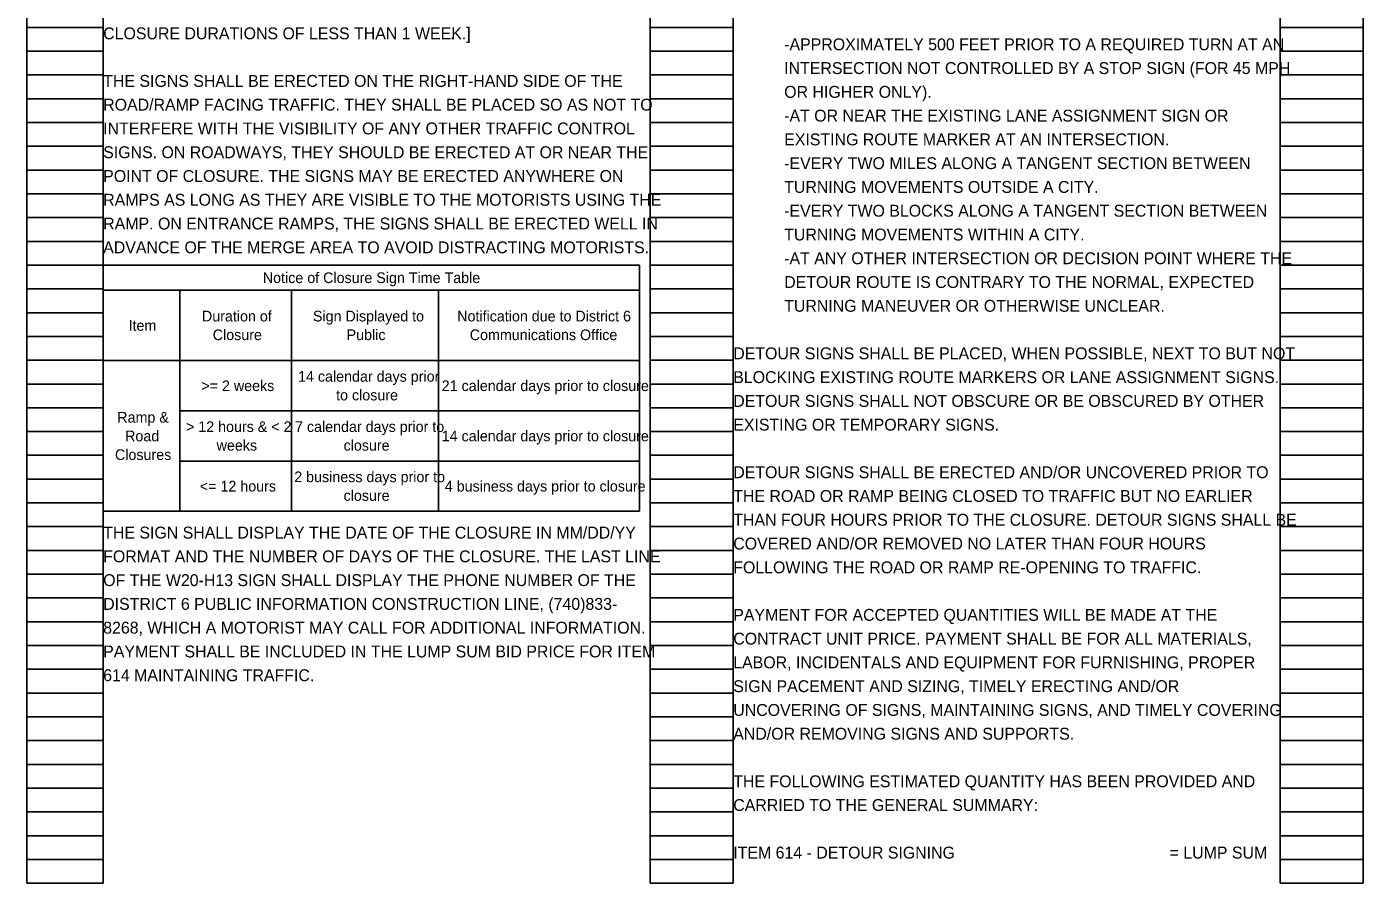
# Model space of a CAD drawing. Extents: x 24172 to 24226.9, y 11011.9 to 11091.2.
# Drawn here: x 24196.45 to 24212.19, y 11041.95 to 11052.04 of the extents above; entities that cross this region are included whole.
import ezdxf

# ---------------------------------------------------------------- set-up
doc = ezdxf.new("R2010")
doc.units = 0
doc.layers.add('SC_Scratch1', color=7, linetype='Continuous')
doc.layers.add('SH_Data', color=7, linetype='Continuous')

msp = doc.modelspace()

# ---------------------------------------------------------------- linework, layer by layer
at = {"layer": 'SC_Scratch1'}
for p, q in [((24197.35, 11049.227), (24203.665, 11049.227)), ((24197.35, 11049.227), (24197.35, 11046.328)), ((24203.665, 11049.227), (24203.665, 11046.328)), ((24197.35, 11048.931), (24203.665, 11048.931)), ((24198.252, 11048.931), (24198.252, 11046.328)), ((24199.568, 11048.931), (24199.568, 11046.328)), ((24201.299, 11048.931), (24201.299, 11046.328)), ((24197.35, 11048.103), (24203.665, 11048.103)), ((24198.252, 11047.511), (24203.665, 11047.511)), ((24198.252, 11046.919), (24203.665, 11046.919)), ((24197.35, 11046.328), (24203.665, 11046.328))]:
    msp.add_line(p, q, dxfattribs=at)
at = {"layer": 'SH_Data'}
for p, q in [((24196.45, 11041.947), (24196.45, 11062.107)), ((24197.35, 11041.947), (24197.35, 11062.107)), ((24203.79, 11041.947), (24203.79, 11062.107)), ((24204.77, 11041.947), (24204.77, 11062.107)), ((24211.21, 11041.947), (24211.21, 11062.107)), ((24212.19, 11041.947), (24212.19, 11062.107)), ((24196.45, 11052.027), (24197.35, 11052.027)), ((24203.79, 11052.027), (24204.77, 11052.027)), ((24211.21, 11052.027), (24212.19, 11052.027)), ((24196.45, 11051.747), (24197.35, 11051.747)), ((24203.79, 11051.747), (24204.77, 11051.747)), ((24211.21, 11051.747), (24212.19, 11051.747)), ((24196.45, 11051.467), (24197.35, 11051.467)), ((24203.79, 11051.467), (24204.77, 11051.467)), ((24211.21, 11051.467), (24212.19, 11051.467)), ((24196.45, 11051.187), (24197.35, 11051.187)), ((24203.79, 11051.187), (24204.77, 11051.187)), ((24211.21, 11051.187), (24212.19, 11051.187)), ((24196.45, 11050.907), (24197.35, 11050.907)), ((24203.79, 11050.907), (24204.77, 11050.907)), ((24211.21, 11050.907), (24212.19, 11050.907)), ((24196.45, 11050.627), (24197.35, 11050.627)), ((24203.79, 11050.627), (24204.77, 11050.627)), ((24211.21, 11050.627), (24212.19, 11050.627)), ((24196.45, 11050.347), (24197.35, 11050.347)), ((24203.79, 11050.347), (24204.77, 11050.347)), ((24211.21, 11050.347), (24212.19, 11050.347)), ((24196.45, 11050.067), (24197.35, 11050.067)), ((24203.79, 11050.067), (24204.77, 11050.067)), ((24211.21, 11050.067), (24212.19, 11050.067)), ((24196.45, 11049.787), (24197.35, 11049.787)), ((24203.79, 11049.787), (24204.77, 11049.787)), ((24211.21, 11049.787), (24212.19, 11049.787)), ((24196.45, 11049.507), (24197.35, 11049.507)), ((24203.79, 11049.507), (24204.77, 11049.507)), ((24211.21, 11049.507), (24212.19, 11049.507)), ((24196.45, 11049.227), (24197.35, 11049.227)), ((24203.79, 11049.227), (24204.77, 11049.227)), ((24211.21, 11049.227), (24212.19, 11049.227)), ((24196.45, 11048.947), (24197.35, 11048.947)), ((24203.79, 11048.947), (24204.77, 11048.947)), ((24211.21, 11048.947), (24212.19, 11048.947)), ((24196.45, 11048.667), (24197.35, 11048.667)), ((24203.79, 11048.667), (24204.77, 11048.667)), ((24211.21, 11048.667), (24212.19, 11048.667)), ((24196.45, 11048.387), (24197.35, 11048.387)), ((24203.79, 11048.387), (24204.77, 11048.387)), ((24211.21, 11048.387), (24212.19, 11048.387)), ((24196.45, 11048.107), (24197.35, 11048.107)), ((24203.79, 11048.107), (24204.77, 11048.107)), ((24211.21, 11048.107), (24212.19, 11048.107)), ((24196.45, 11047.827), (24197.35, 11047.827)), ((24203.79, 11047.827), (24204.77, 11047.827)), ((24211.21, 11047.827), (24212.19, 11047.827)), ((24196.45, 11047.547), (24197.35, 11047.547)), ((24203.79, 11047.547), (24204.77, 11047.547)), ((24211.21, 11047.547), (24212.19, 11047.547)), ((24196.45, 11047.267), (24197.35, 11047.267)), ((24203.79, 11047.267), (24204.77, 11047.267)), ((24211.21, 11047.267), (24212.19, 11047.267)), ((24196.45, 11046.987), (24197.35, 11046.987)), ((24203.79, 11046.987), (24204.77, 11046.987)), ((24211.21, 11046.987), (24212.19, 11046.987)), ((24196.45, 11046.707), (24197.35, 11046.707)), ((24203.79, 11046.707), (24204.77, 11046.707)), ((24211.21, 11046.707), (24212.19, 11046.707)), ((24196.45, 11046.427), (24197.35, 11046.427)), ((24203.79, 11046.427), (24204.77, 11046.427)), ((24211.21, 11046.427), (24212.19, 11046.427)), ((24196.45, 11046.147), (24197.35, 11046.147)), ((24203.79, 11046.147), (24204.77, 11046.147)), ((24211.21, 11046.147), (24212.19, 11046.147)), ((24196.45, 11045.867), (24197.35, 11045.867)), ((24203.79, 11045.867), (24204.77, 11045.867)), ((24211.21, 11045.867), (24212.19, 11045.867)), ((24196.45, 11045.587), (24197.35, 11045.587)), ((24203.79, 11045.587), (24204.77, 11045.587)), ((24211.21, 11045.587), (24212.19, 11045.587)), ((24196.45, 11045.307), (24197.35, 11045.307)), ((24203.79, 11045.307), (24204.77, 11045.307)), ((24211.21, 11045.307), (24212.19, 11045.307)), ((24196.45, 11045.027), (24197.35, 11045.027)), ((24203.79, 11045.027), (24204.77, 11045.027)), ((24211.21, 11045.027), (24212.19, 11045.027)), ((24196.45, 11044.747), (24197.35, 11044.747)), ((24203.79, 11044.747), (24204.77, 11044.747)), ((24211.21, 11044.747), (24212.19, 11044.747)), ((24196.45, 11044.467), (24197.35, 11044.467)), ((24203.79, 11044.467), (24204.77, 11044.467)), ((24211.21, 11044.467), (24212.19, 11044.467)), ((24196.45, 11044.187), (24197.35, 11044.187)), ((24203.79, 11044.187), (24204.77, 11044.187)), ((24211.21, 11044.187), (24212.19, 11044.187)), ((24196.45, 11043.907), (24197.35, 11043.907)), ((24203.79, 11043.907), (24204.77, 11043.907)), ((24211.21, 11043.907), (24212.19, 11043.907)), ((24196.45, 11043.627), (24197.35, 11043.627)), ((24203.79, 11043.627), (24204.77, 11043.627)), ((24211.21, 11043.627), (24212.19, 11043.627)), ((24196.45, 11043.347), (24197.35, 11043.347)), ((24203.79, 11043.347), (24204.77, 11043.347)), ((24211.21, 11043.347), (24212.19, 11043.347)), ((24196.45, 11043.067), (24197.35, 11043.067)), ((24203.79, 11043.067), (24204.77, 11043.067)), ((24211.21, 11043.067), (24212.19, 11043.067)), ((24196.45, 11042.787), (24197.35, 11042.787)), ((24203.79, 11042.787), (24204.77, 11042.787)), ((24211.21, 11042.787), (24212.19, 11042.787)), ((24196.45, 11042.507), (24197.35, 11042.507)), ((24203.79, 11042.507), (24204.77, 11042.507)), ((24211.21, 11042.507), (24212.19, 11042.507)), ((24196.45, 11042.227), (24197.35, 11042.227)), ((24203.79, 11042.227), (24204.77, 11042.227)), ((24211.21, 11042.227), (24212.19, 11042.227)), ((24196.45, 11041.947), (24197.35, 11041.947)), ((24203.79, 11041.947), (24204.77, 11041.947)), ((24211.21, 11041.947), (24212.19, 11041.947))]:
    msp.add_line(p, q, dxfattribs=at)

# ---------------------------------------------------------------- texts
at = {"layer": 'SC_Scratch1'}
for s, height, p in [('CLOSURE DURATIONS OF LESS THAN 1 WEEK.]', 0.14, (24197.35, 11051.887)), ('.', 0.14, (24201.438, 11051.887)), ('-APPROXIMATELY 500 FEET PRIOR TO A REQUIRED TURN AT AN ', 0.14, (24205.37, 11051.758)), ('INTERSECTION NOT CONTROLLED BY A STOP SIGN (FOR 45 MPH ', 0.14, (24205.37, 11051.478)), ('THE SIGNS SHALL BE ERECTED ON THE RIGHT-HAND SIDE OF THE ', 0.14, (24197.35, 11051.327)), ('OR HIGHER ONLY).', 0.14, (24205.37, 11051.198)), ('ROAD/RAMP FACING TRAFFIC. THEY SHALL BE PLACED SO AS NOT TO ', 0.14, (24197.35, 11051.047)), ('-AT OR NEAR THE EXISTING LANE ASSIGNMENT SIGN OR ', 0.14, (24205.37, 11050.918)), ('INTERFERE WITH THE VISIBILITY OF ANY OTHER TRAFFIC CONTROL ', 0.14, (24197.35, 11050.767)), ('EXISTING ROUTE MARKER AT AN INTERSECTION.', 0.14, (24205.37, 11050.638)), ('SIGNS. ON ROADWAYS, THEY SHOULD BE ERECTED AT OR NEAR THE ', 0.14, (24197.35, 11050.487)), ('-EVERY TWO MILES ALONG A TANGENT SECTION BETWEEN ', 0.14, (24205.37, 11050.358)), ('POINT OF CLOSURE. THE SIGNS MAY BE ERECTED ANYWHERE ON ', 0.14, (24197.35, 11050.207)), ('TURNING MOVEMENTS OUTSIDE A CITY.', 0.14, (24205.37, 11050.078)), ('RAMPS AS LONG AS THEY ARE VISIBLE TO THE MOTORISTS USING THE ', 0.14, (24197.35, 11049.927)), ('-EVERY TWO BLOCKS ALONG A TANGENT SECTION BETWEEN ', 0.14, (24205.37, 11049.798)), ('RAMP. ON ENTRANCE RAMPS, THE SIGNS SHALL BE ERECTED WELL IN ', 0.14, (24197.35, 11049.647)), ('TURNING MOVEMENTS WITHIN A CITY.', 0.14, (24205.37, 11049.518)), ('ADVANCE OF THE MERGE AREA TO AVOID DISTRACTING MOTORISTS.', 0.14, (24197.35, 11049.367)), ('-AT ANY OTHER INTERSECTION OR DECISION POINT WHERE THE ', 0.14, (24205.37, 11049.238)), ('Notice of Closure Sign Time Table', 0.12573, (24199.23, 11049.016)), ('DETOUR ROUTE IS CONTRARY TO THE NORMAL, EXPECTED ', 0.14, (24205.37, 11048.958)), ('Duration of ', 0.12573, (24198.513, 11048.564)), ('Sign Displayed to ', 0.12573, (24199.82, 11048.564)), ('Notification due to District 6 ', 0.12573, (24201.519, 11048.564)), ('TURNING MANEUVER OR OTHERWISE UNCLEAR.', 0.14, (24205.37, 11048.678)), ('Item', 0.1257, (24197.649, 11048.454)), ('Closure', 0.1257, (24198.64, 11048.344)), ('Public', 0.1257, (24200.217, 11048.344)), ('Communications Office', 0.12573, (24201.667, 11048.344)), ('DETOUR SIGNS SHALL BE PLACED, WHEN POSSIBLE, NEXT TO BUT NOT ', 0.14, (24204.77, 11048.118)), ('14 calendar days prior ', 0.12573, (24199.645, 11047.854)), ('BLOCKING EXISTING ROUTE MARKERS OR LANE ASSIGNMENT SIGNS. ', 0.14, (24204.77, 11047.838)), ('>= 2 weeks', 0.1257, (24198.506, 11047.744)), ('to closure', 0.1257, (24200.093, 11047.634)), ('21 calendar days prior to closure', 0.12573, (24201.337, 11047.744)), ('DETOUR SIGNS SHALL NOT OBSCURE OR BE OBSCURED BY OTHER ', 0.14, (24204.77, 11047.558)), ('Ramp & ', 0.1257, (24197.516, 11047.372)), ('Road ', 0.1257, (24197.608, 11047.152)), ('> 12 hours & < 2 ', 0.12573, (24198.325, 11047.262)), ('7 calendar days prior to ', 0.12573, (24199.609, 11047.262)), ('14 calendar days prior to closure', 0.12573, (24201.337, 11047.152)), ('EXISTING OR TEMPORARY SIGNS.', 0.14, (24204.77, 11047.278)), ('weeks', 0.1257, (24198.686, 11047.042)), ('closure', 0.1257, (24200.181, 11047.042)), ('Closures', 0.1257, (24197.489, 11046.932)), ('DETOUR SIGNS SHALL BE ERECTED AND/OR UNCOVERED PRIOR TO ', 0.14, (24204.77, 11046.718)), ('<= 12 hours', 0.12573, (24198.488, 11046.561)), ('2 business days prior to ', 0.12573, (24199.6, 11046.671)), ('4 business days prior to closure', 0.12573, (24201.373, 11046.561)), ('closure', 0.1257, (24200.181, 11046.451)), ('THE ROAD OR RAMP BEING CLOSED TO TRAFFIC BUT NO EARLIER ', 0.14, (24204.77, 11046.438)), ('THAN FOUR HOURS PRIOR TO THE CLOSURE. DETOUR SIGNS SHALL BE ', 0.14, (24204.77, 11046.158)), ('THE SIGN SHALL DISPLAY THE DATE OF THE CLOSURE IN MM/DD/YY ', 0.14, (24197.35, 11046.007)), ('COVERED AND/OR REMOVED NO LATER THAN FOUR HOURS ', 0.14, (24204.77, 11045.878)), ('FORMAT AND THE NUMBER OF DAYS OF THE CLOSURE. THE LAST LINE ', 0.14, (24197.35, 11045.727)), ('FOLLOWING THE ROAD OR RAMP RE-OPENING TO TRAFFIC.', 0.14, (24204.77, 11045.598)), ('OF THE W20-H13 SIGN SHALL DISPLAY THE PHONE NUMBER OF THE ', 0.14, (24197.35, 11045.447)), ('DISTRICT 6 PUBLIC INFORMATION CONSTRUCTION LINE, (740)833-', 0.14, (24197.35, 11045.167)), ('PAYMENT FOR ACCEPTED QUANTITIES WILL BE MADE AT THE ', 0.14, (24204.77, 11045.038)), ('8268, WHICH A MOTORIST MAY CALL FOR ADDITIONAL INFORMATION. ', 0.14, (24197.35, 11044.887)), ('CONTRACT UNIT PRICE. PAYMENT SHALL BE FOR ALL MATERIALS, ', 0.14, (24204.77, 11044.758)), ('PAYMENT SHALL BE INCLUDED IN THE LUMP SUM BID PRICE FOR ITEM ', 0.14, (24197.35, 11044.607)), ('LABOR, INCIDENTALS AND EQUIPMENT FOR FURNISHING, PROPER ', 0.14, (24204.77, 11044.478)), ('614 MAINTAINING TRAFFIC.', 0.14, (24197.35, 11044.327)), ('SIGN PACEMENT AND SIZING, TIMELY ERECTING AND/OR ', 0.14, (24204.77, 11044.198)), ('UNCOVERING OF SIGNS, MAINTAINING SIGNS, AND TIMELY COVERING ', 0.14, (24204.77, 11043.918)), ('AND/OR REMOVING SIGNS AND SUPPORTS.', 0.14, (24204.77, 11043.638)), ('THE FOLLOWING ESTIMATED QUANTITY HAS BEEN PROVIDED AND ', 0.14, (24204.77, 11043.078)), ('CARRIED TO THE GENERAL SUMMARY:', 0.14, (24204.77, 11042.798)), ('ITEM 614 - DETOUR SIGNING', 0.14, (24204.77, 11042.238)), ('= LUMP SUM', 0.14, (24209.909, 11042.238))]:
    msp.add_text(s, height=height, dxfattribs=at).set_placement(p)

doc.saveas('drawing.dxf')
